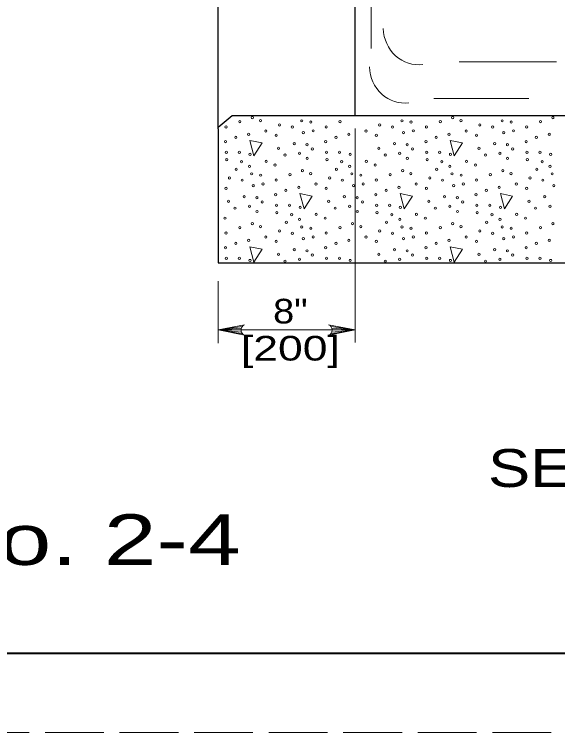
# Model space of a CAD drawing. Extents: x 1083.1 to 1117.1, y 697.4 to 719.4.
# Drawn here: x 1099.924 to 1103.363, y 697.354 to 701.901 of the extents above; entities that cross this region are included whole.
import ezdxf
from ezdxf.enums import TextEntityAlignment as Align

# ---------------------------------------------------------------- set-up
doc = ezdxf.new("R2010")
doc.units = 0
doc.header["$LTSCALE"] = 0.062
doc.linetypes.add('LONG_DASHED', pattern=[7.5, 6, -1.5])
doc.layers.add('1', color=7, linetype='Continuous', lineweight=13)

msp = doc.modelspace()

# ---------------------------------------------------------------- linework, layer by layer
at = {"layer": '1', "lineweight": 25}
for p, q in [((1101.2135, 701.176), (1101.2135, 705.44767)), ((1102.08108, 701.25917), (1102.08108, 705.36217)), ((1101.303, 701.25917), (1101.21342, 701.18583)), ((1106.76642, 701.25917), (1101.303, 701.25917))]:
    msp.add_line(p, q, dxfattribs=at)
at = {"layer": '1'}
for p, q in [((1102.18375, 701.68542), (1102.18375, 702.66567)), ((1102.73925, 701.60142), (1103.3565, 701.60142)), ((1102.5805, 701.368), (1103.18017, 701.368)), ((1102.08108, 701.17908), (1102.08108, 699.82483)), ((1101.2135, 700.2115), (1101.2135, 699.8205)), ((1101.36583, 699.9245), (1101.2135, 699.90317)), ((1101.36067, 699.91392), (1101.2135, 699.90317)), ((1101.2135, 699.90317), (1102.08108, 699.90317)), ((1101.35908, 699.90317), (1101.2135, 699.90317)), ((1101.36175, 699.8895), (1101.2135, 699.90317)), ((1101.36758, 699.87967), (1101.2135, 699.90317)), ((1101.927, 699.87967), (1102.08108, 699.90317)), ((1101.92875, 699.9245), (1102.08108, 699.90317)), ((1101.93283, 699.8895), (1102.08108, 699.90317)), ((1101.93392, 699.91392), (1102.08108, 699.90317)), ((1101.9355, 699.90317), (1102.08108, 699.90317))]:
    msp.add_line(p, q, dxfattribs=at)
at = {"layer": '1', "linetype": 'LONG_DASHED'}
msp.add_lwpolyline([(1083.12642, 697.35408), (1117.12642, 697.35408), (1117.12642, 719.35408), (1083.12642, 719.35408)], close=True, dxfattribs=at)
at = {"layer": '1', "lineweight": 25}
for points in [[(1116.62642, 697.85408), (1085.12642, 697.85408), (1085.12642, 718.85408)], [(1101.2135, 701.176), (1101.2135, 700.328), (1106.86575, 700.328), (1106.86575, 701.19417)]]:
    msp.add_lwpolyline(points, dxfattribs=at)
at = {"layer": '1', "lineweight": 40}
msp.add_lwpolyline([(1085.12642, 718.85408), (1116.62642, 718.85408), (1116.62642, 697.85408), (1085.12642, 697.85408)], close=True, dxfattribs=at)
msp.add_lwpolyline([(1085.12642, 718.85408), (1116.62642, 718.85408), (1116.62642, 697.85408), (1085.12642, 697.85408)], close=True, dxfattribs=at)
at = {"layer": '1'}
for points in [[(1101.41492, 701.1025), (1101.44058, 701.00517), (1101.49275, 701.08733)], [(1102.68367, 701.1025), (1102.70933, 701.00517), (1102.76158, 701.08733)], [(1101.73208, 700.76667), (1101.75775, 700.66925), (1101.81, 700.75142)], [(1102.3665, 700.76667), (1102.39217, 700.66925), (1102.44433, 700.75142)], [(1103.00092, 700.76667), (1103.02658, 700.66925), (1103.07875, 700.75142)], [(1101.41492, 700.43075), (1101.44058, 700.3335), (1101.49275, 700.41567)], [(1102.68367, 700.43075), (1102.70933, 700.3335), (1102.76158, 700.41567)]]:
    msp.add_lwpolyline(points, close=True, dxfattribs=at)
for points in [[(1101.38175, 699.8695), (1101.2135, 699.90317), (1101.38175, 699.93683)], [(1101.91283, 699.8695), (1102.08108, 699.90317), (1101.91283, 699.93683)]]:
    msp.add_lwpolyline(points, dxfattribs=at)
for centre, start, end in [((1101.39531, 699.90322), 112.08782, 247.91395), ((1101.89927, 699.90322), 292.08605, 67.91218)]:
    msp.add_arc(centre, 0.03631, start, end, dxfattribs=at)
for centre in [(1102.48353, 701.82019), (1102.39539, 701.57742)]:
    msp.add_ellipse(centre, major_axis=(0, 0.23746), ratio=0.944544, start_param=1.6092515, end_param=3.2607675, dxfattribs=at)
for centre in [(1101.43039, 701.24809), (1102.69919, 701.24809), (1103.33359, 701.24809), (1101.35156, 701.22274), (1101.48262, 701.22906), (1101.60252, 701.20186), (1101.74331, 701.22755), (1101.80067, 701.21933), (1101.98596, 701.22274), (1102.23692, 701.20186), (1102.37771, 701.22755), (1102.43507, 701.21933), (1102.62037, 701.22274), (1102.75142, 701.22906), (1102.87133, 701.20186), (1103.01211, 701.22755), (1103.06947, 701.21933), (1103.25477, 701.22274), (1101.26391, 701.18849), (1101.51598, 701.16285), (1101.6833, 701.18765), (1101.8152, 701.16408), (1101.89831, 701.18849), (1102.15038, 701.16285), (1102.3177, 701.18765), (1102.44961, 701.16408), (1102.53271, 701.18849), (1102.78478, 701.16285), (1102.95211, 701.18765), (1103.08401, 701.16408), (1103.16712, 701.18849), (1101.32582, 701.12294), (1101.40723, 701.14197), (1101.58111, 701.13565), (1101.75351, 701.15317), (1101.96022, 701.12294), (1102.04163, 701.14197), (1102.21551, 701.13565), (1102.38791, 701.15317), (1102.59462, 701.12294), (1102.67604, 701.14197), (1102.84991, 701.13565), (1103.02231, 701.15317), (1103.22902, 701.12294), (1103.31044, 701.14197), (1101.26079, 701.09574), (1101.69588, 701.08309), (1101.77672, 701.0761), (1101.89519, 701.09574), (1102.33029, 701.08309), (1102.41112, 701.0761), (1102.52959, 701.09574), (1102.96469, 701.08309), (1103.04552, 701.0761), (1103.164, 701.09574), (1101.26592, 701.02863), (1101.34818, 701.02863), (1101.59655, 701.05404), (1101.7293, 701.02231), (1101.81039, 701.04951), (1101.90032, 701.02863), (1101.98258, 701.02863), (1102.23095, 701.05404), (1102.3637, 701.02231), (1102.4448, 701.04951), (1102.53472, 701.02863), (1102.61698, 701.02863), (1102.86535, 701.05404), (1102.9981, 701.02231), (1103.0792, 701.04951), (1103.16912, 701.02863), (1103.25138, 701.02863), (1101.26846, 700.9824), (1101.4158, 701.01503), (1101.63768, 701.0105), (1101.77756, 700.98934), (1101.90286, 700.9824), (1102.0502, 701.01503), (1102.27208, 701.0105), (1102.41197, 700.98934), (1102.53726, 700.9824), (1102.6846, 701.01503), (1102.90648, 701.0105), (1103.04637, 700.98934), (1103.17166, 700.9824), (1103.319, 701.01503), (1101.36187, 700.9688), (1101.41236, 700.93886), (1101.51772, 700.97059), (1101.57424, 700.94703), (1101.99627, 700.9688), (1102.04676, 700.93886), (1102.15212, 700.97059), (1102.20864, 700.94703), (1102.63068, 700.9688), (1102.68116, 700.93886), (1102.78653, 700.97059), (1102.84304, 700.94703), (1103.26508, 700.9688), (1103.31557, 700.93886), (1101.32841, 700.92072), (1101.4261, 700.89173), (1101.48346, 700.8835), (1101.66876, 700.88692), (1101.74759, 700.91227), (1101.79982, 700.89324), (1101.96281, 700.92072), (1102.06051, 700.89173), (1102.11787, 700.8835), (1102.30317, 700.88692), (1102.38199, 700.91227), (1102.43422, 700.89324), (1102.59721, 700.92072), (1102.69491, 700.89173), (1102.75227, 700.8835), (1102.93757, 700.88692), (1103.01639, 700.91227), (1103.06862, 700.89324), (1103.23161, 700.92072), (1103.32931, 700.89173), (1101.28532, 700.86604), (1101.3661, 700.85182), (1101.58111, 700.85266), (1101.91972, 700.86604), (1102.0005, 700.85182), (1102.21551, 700.85266), (1102.55412, 700.86604), (1102.6349, 700.85182), (1102.84991, 700.85266), (1103.18853, 700.86604), (1103.26931, 700.85182), (1101.26391, 700.79982), (1101.43631, 700.81734), (1101.498, 700.82826), (1101.72443, 700.80615), (1101.83318, 700.82703), (1101.89831, 700.79982), (1102.07071, 700.81734), (1102.13241, 700.82826), (1102.35883, 700.80615), (1102.46758, 700.82703), (1102.53271, 700.79982), (1102.70511, 700.81734), (1102.76681, 700.82826), (1102.99324, 700.80615), (1103.10198, 700.82703), (1103.16712, 700.79982), (1103.33951, 700.81734), (1101.37868, 700.74727), (1101.57799, 700.75992), (1101.64302, 700.78712), (1102.01308, 700.74727), (1102.21239, 700.75992), (1102.27742, 700.78712), (1102.64749, 700.74727), (1102.8468, 700.75992), (1102.91182, 700.78712), (1103.28189, 700.74727), (1101.27935, 700.71822), (1101.45952, 700.74027), (1101.49319, 700.71369), (1101.91375, 700.71822), (1102.09392, 700.74027), (1102.12759, 700.71369), (1102.54815, 700.71822), (1102.72832, 700.74027), (1102.762, 700.71369), (1103.18255, 700.71822), (1101.32048, 700.67467), (1101.41209, 700.68648), (1101.46036, 700.65352), (1101.58312, 700.69281), (1101.66538, 700.69281), (1101.733, 700.67921), (1101.95488, 700.67467), (1102.0465, 700.68648), (1102.09476, 700.65352), (1102.21752, 700.69281), (1102.29978, 700.69281), (1102.3674, 700.67921), (1102.58928, 700.67467), (1102.6809, 700.68648), (1102.72917, 700.65352), (1102.85192, 700.69281), (1102.93418, 700.69281), (1103.0018, 700.67921), (1103.22368, 700.67467), (1103.3153, 700.68648), (1101.25704, 700.6112), (1101.58566, 700.64658), (1101.67907, 700.63298), (1101.83492, 700.63477), (1101.89144, 700.6112), (1102.22006, 700.64658), (1102.31347, 700.63298), (1102.46933, 700.63477), (1102.52584, 700.6112), (1102.85446, 700.64658), (1102.94788, 700.63298), (1103.10373, 700.63477), (1103.16024, 700.6112), (1101.43039, 700.57645), (1101.64561, 700.5849), (1101.72956, 700.60303), (1102.06479, 700.57645), (1102.28001, 700.5849), (1102.36396, 700.60303), (1102.69919, 700.57645), (1102.91441, 700.5849), (1102.99836, 700.60303), (1103.33359, 700.57645), (1101.26391, 700.51684), (1101.35156, 700.55109), (1101.48262, 700.55742), (1101.60252, 700.53021), (1101.74331, 700.5559), (1101.80067, 700.54768), (1101.89831, 700.51684), (1101.98596, 700.55109), (1102.11702, 700.55742), (1102.23692, 700.53021), (1102.37771, 700.5559), (1102.43507, 700.54768), (1102.53271, 700.51684), (1102.62037, 700.55109), (1102.75142, 700.55742), (1102.87133, 700.53021), (1103.01211, 700.5559), (1103.06947, 700.54768), (1103.16712, 700.51684), (1103.25477, 700.55109), (1101.51598, 700.4912), (1101.6833, 700.516), (1101.75351, 700.48152), (1101.8152, 700.49243), (1102.15038, 700.4912), (1102.3177, 700.516), (1102.38791, 700.48152), (1102.44961, 700.49243), (1102.78478, 700.4912), (1102.95211, 700.516), (1103.02231, 700.48152), (1103.08401, 700.49243), (1101.32582, 700.45129), (1101.40723, 700.47032), (1101.58111, 700.464), (1101.96022, 700.45129), (1102.04163, 700.47032), (1102.21551, 700.464), (1102.59462, 700.45129), (1102.67604, 700.47032), (1102.84991, 700.464), (1103.22902, 700.45129), (1103.31044, 700.47032), (1101.26079, 700.42409), (1101.59655, 700.38239), (1101.69588, 700.41144), (1101.77672, 700.40445), (1101.89519, 700.42409), (1102.23095, 700.38239), (1102.33029, 700.41144), (1102.41112, 700.40445), (1102.52959, 700.42409), (1102.86535, 700.38239), (1102.96469, 700.41144), (1103.04552, 700.40445), (1103.164, 700.42409), (1101.26592, 700.35698), (1101.34818, 700.35698), (1101.4158, 700.34338), (1101.63768, 700.33885), (1101.7293, 700.35066), (1101.81039, 700.37786), (1101.90032, 700.35698), (1101.98258, 700.35698), (1102.0502, 700.34338), (1102.27208, 700.33885), (1102.3637, 700.35066), (1102.4448, 700.37786), (1102.53472, 700.35698), (1102.61698, 700.35698), (1102.6846, 700.34338), (1102.90648, 700.33885), (1102.9981, 700.35066), (1103.0792, 700.37786), (1103.16912, 700.35698), (1103.25138, 700.35698), (1103.319, 700.34338)]:
    msp.add_ellipse(centre, major_axis=(0, 0.00718), ratio=0.944544, dxfattribs=at)

# ---------------------------------------------------------------- texts
for s, height, width, p in [('8"', 0.156, 1.15, (1101.67133, 699.9445)), ('[200]', 0.156, 1.35, (1101.67133, 699.70983)), ('CATCH BASINS No. 2-3 & No. 2-4', 0.32, 1.4, (1096.72875, 698.41617))]:
    msp.add_text(s, height=height, dxfattribs=dict(at, width=width)).set_placement(p, align=Align.CENTER)
at = {"layer": '1', "width": 1.25}
msp.add_text('SECTION C-C', height=0.24, dxfattribs=at).set_placement((1102.92242, 698.90933))

doc.saveas('drawing.dxf')
